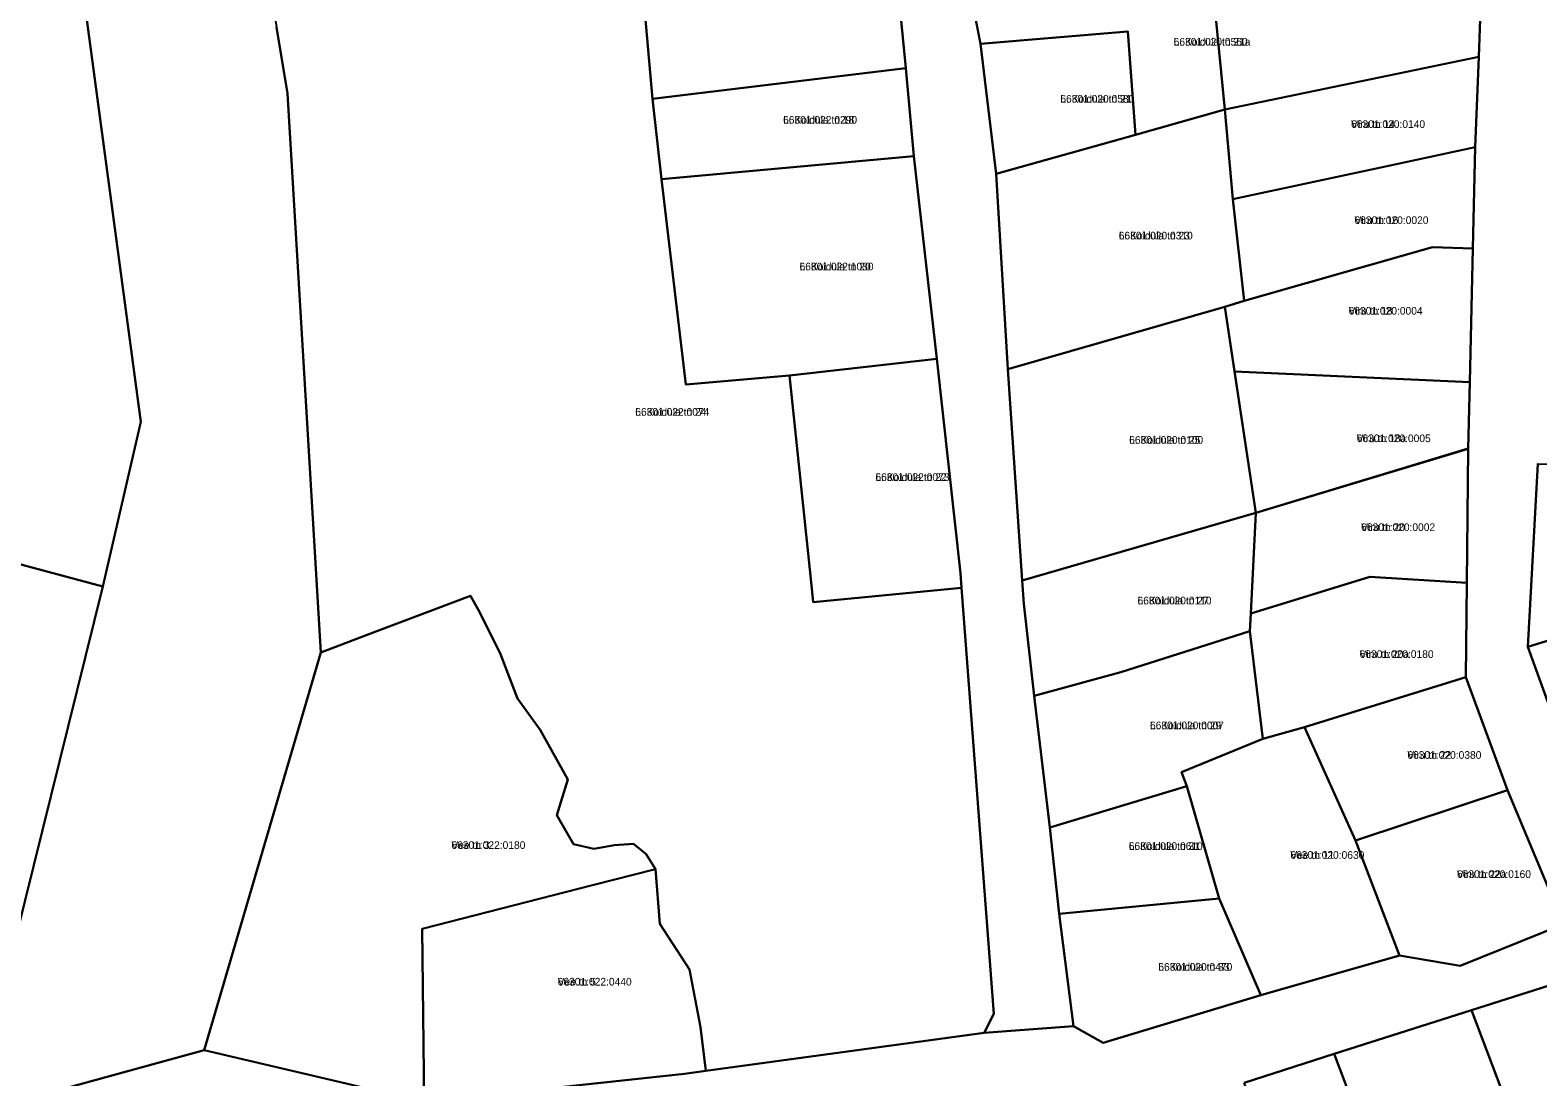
# Model space of a CAD drawing. Extents: x 632278 to 636344, y 6578401 to 6583362.
# Drawn here: x 634226.1 to 634521.7, y 6580277.2 to 6580482.5 of the extents above; entities that cross this region are included whole.
import ezdxf

# ---------------------------------------------------------------- set-up
doc = ezdxf.new("R2010")
doc.units = 0
for name, color, linetype in [('L_AADRESS', 7, 'Continuous'), ('PIIR', 7, 'Continuous'), ('TUNNUS', 7, 'Continuous')]:
    doc.layers.add(name, color=color, linetype=linetype)

msp = doc.modelspace()

# ---------------------------------------------------------------- linework, layer by layer
at = {"layer": 'PIIR'}
for points in [[(634225.23, 6581067.6), (634226.68, 6581036.58), (634227.15, 6581025.28), (634228.16, 6581005.67), (634228.8, 6580993.57), (634229.91, 6580974.72), (634244.55, 6580754.47), (634246.36, 6580732.87), (634249.81, 6580666.52), (634250.81, 6580645.38), (634251.04, 6580641.51), (634252.34, 6580620.25), (634253.83, 6580589.78), (634265.55, 6580590.45), (634266.51, 6580570.25), (634267.07, 6580555.4), (634269.03, 6580516.69), (634274.45, 6580483.07), (634276.55, 6580470.05), (634283.11, 6580360.46), (634260.23, 6580282.49), (634233.12, 6580275.05), (634231.27, 6580268.29), (634222.04, 6580222.66)], [(634526.67, 6580307.21), (634515.73, 6580333.47), (634507.57, 6580355.65), (634507.77, 6580374.1), (634507.99, 6580400.42), (634508, 6580400.43), (634508.3, 6580413.48), (634508.93, 6580439.68), (634509.35, 6580459.54), (634510.12, 6580477.29), (634511.32, 6580512.4), (634511.77, 6580518.86), (634513.89, 6580546.25), (634515.85, 6580575.04), (634516.75, 6580605.53), (634519.64, 6580660.19), (634521.37, 6580706.15), (634531.46, 6580696.5)], [(634220.01, 6580291.27), (634240.38, 6580373.39), (634247.86, 6580405.68), (634225.27, 6580573.66)], [(634411.11, 6580486.45), (634412.41, 6580479.83), (634415.51, 6580454.35), (634417.77, 6580416), (634420.6, 6580374.56), (634420.92, 6580370.01), (634422.93, 6580351.93), (634426.03, 6580326.16), (634427.86, 6580309.24), (634430.64, 6580287.21), (634413.16, 6580285.87), (634415.04, 6580289.63), (634408.7, 6580373.13), (634408.48, 6580376), (634403.88, 6580418.04), (634399.34, 6580457.77), (634397.78, 6580475.03), (634395.68, 6580496.5)], [(634346.16, 6580491.24), (634348.14, 6580469.06), (634349.9, 6580453.29), (634354.65, 6580413.01), (634374.96, 6580414.78), (634379.36, 6580372.99), (634379.61, 6580370.34), (634408.7, 6580373.13), (634415.04, 6580289.63), (634413.16, 6580285.87), (634364.33, 6580279.21), (634358.57, 6580278.43), (634357.56, 6580287.01), (634355.4, 6580298.27), (634349.53, 6580307.22), (634348.72, 6580317.96), (634346.85, 6580320.89), (634344.43, 6580322.96), (634340.66, 6580322.67), (634336.65, 6580321.94), (634332.63, 6580322.9), (634329.35, 6580328.55), (634331.55, 6580335.58), (634326.09, 6580345.26), (634321.64, 6580351.43), (634318.31, 6580360.16), (634314.27, 6580368.32), (634312.47, 6580371.55), (634293.57, 6580364.44), (634283.11, 6580360.46), (634276.55, 6580470.05), (634274.45, 6580483.07)], [(634521.68, 6580397.48), (634519.71, 6580361.56), (634529.07, 6580335.73)], [(634233.12, 6580275.05), (634260.23, 6580282.49), (634303.37, 6580272.33), (634354.37, 6580277.83), (634358.57, 6580278.43), (634364.33, 6580279.21), (634413.16, 6580285.87), (634430.64, 6580287.21), (634436.43, 6580283.88), (634467.33, 6580293.27), (634494.51, 6580301.07), (634506.43, 6580299.02), (634526.67, 6580307.21)], [(634530.69, 6580297.31), (634508.64, 6580290.29), (634481.72, 6580281.73), (634464.09, 6580276.05)]]:
    msp.add_lwpolyline(points, dxfattribs=at)
for points in [[(634105.62, 6580560.24), (634104.57, 6580571.84), (634217.05, 6580579.98), (634220.12, 6580579.79), (634223.06, 6580577.61), (634225.27, 6580573.66), (634247.86, 6580405.68), (634240.38, 6580373.39), (634180.67, 6580389.44), (634076.26, 6580417.52), (634075.51, 6580432.84), (634074.29, 6580470.06), (634073, 6580499.74), (634094.48, 6580500.93), (634090.58, 6580520.33), (634095.58, 6580539.25)], [(634457.38, 6580496.94), (634457.52, 6580500.28), (634511.32, 6580512.4), (634510.12, 6580477.29), (634460.29, 6580466.92)], [(634346.16, 6580491.24), (634355.82, 6580492.47), (634395.68, 6580496.5), (634397.78, 6580475.03), (634348.14, 6580469.06)], [(634441.27, 6580482.24), (634412.41, 6580479.83), (634411.11, 6580486.45), (634457.38, 6580496.94), (634460.29, 6580466.92), (634442.77, 6580462)], [(634412.41, 6580479.83), (634441.27, 6580482.24), (634442.77, 6580462), (634415.51, 6580454.35)], [(634460.29, 6580466.92), (634510.12, 6580477.29), (634509.35, 6580459.54), (634493.61, 6580456.13), (634461.86, 6580449.36)], [(634399.34, 6580457.77), (634349.9, 6580453.29), (634348.14, 6580469.06), (634397.78, 6580475.03)], [(634415.51, 6580454.35), (634442.77, 6580462), (634460.29, 6580466.92), (634461.86, 6580449.36), (634464.1, 6580429.42), (634460.3, 6580428.22), (634417.77, 6580416)], [(634461.86, 6580449.36), (634493.61, 6580456.13), (634509.35, 6580459.54), (634508.93, 6580439.67), (634501.01, 6580439.94), (634464.1, 6580429.42)], [(634349.9, 6580453.29), (634399.34, 6580457.77), (634403.88, 6580418.04), (634374.96, 6580414.78), (634354.65, 6580413.01)], [(634508.93, 6580439.67), (634508.3, 6580413.48), (634462.21, 6580415.57), (634460.3, 6580428.22), (634464.1, 6580429.41), (634501.01, 6580439.94)], [(634417.77, 6580416), (634460.3, 6580428.22), (634466.39, 6580387.85), (634420.6, 6580374.56)], [(634374.96, 6580414.78), (634403.88, 6580418.04), (634408.48, 6580376), (634408.7, 6580373.13), (634379.61, 6580370.34), (634379.36, 6580372.99)], [(634508.3, 6580413.48), (634508, 6580400.43), (634466.39, 6580387.85), (634462.21, 6580415.57)], [(634466.39, 6580387.85), (634507.99, 6580400.42), (634507.77, 6580374.1), (634488.7, 6580375.27), (634465.37, 6580368.13)], [(634519.71, 6580361.56), (634521.68, 6580397.48), (634530.9, 6580397.19), (634530.67, 6580392.63), (634532.84, 6580392.55), (634539.75, 6580392.96), (634544.27, 6580392.91), (634544.18, 6580391.17), (634594.77, 6580397.74), (634597.67, 6580387.25), (634596.4, 6580386.84), (634570.31, 6580378.49), (634541.88, 6580368.41)], [(634180.67, 6580389.44), (634240.38, 6580373.39), (634220.01, 6580291.27), (634216.86, 6580290.73), (634214.42, 6580290.78), (634210.6, 6580291.52), (634187.14, 6580297.94), (634135.36, 6580312.18), (634150.72, 6580367.76), (634173.04, 6580361.59)], [(634422.93, 6580351.93), (634420.92, 6580370.01), (634420.6, 6580374.56), (634466.39, 6580387.85), (634465.37, 6580368.13), (634465.19, 6580364.66), (634439.93, 6580356.57)], [(634507.57, 6580355.65), (634475.92, 6580345.84), (634467.77, 6580343.51), (634465.19, 6580364.66), (634465.37, 6580368.13), (634488.7, 6580375.27), (634507.77, 6580374.1)], [(634283.11, 6580360.46), (634293.57, 6580364.44), (634312.47, 6580371.55), (634314.27, 6580368.32), (634318.31, 6580360.16), (634321.64, 6580351.43), (634326.09, 6580345.26), (634331.55, 6580335.58), (634329.35, 6580328.55), (634332.63, 6580322.9), (634336.65, 6580321.94), (634340.66, 6580322.67), (634344.43, 6580322.96), (634346.85, 6580320.89), (634348.72, 6580317.96), (634336.36, 6580314.86), (634302.95, 6580306.26), (634303.37, 6580272.33), (634260.23, 6580282.49)], [(634519.71, 6580361.56), (634541.88, 6580368.41), (634552.77, 6580343.21), (634529.07, 6580335.73)], [(634422.93, 6580351.93), (634439.93, 6580356.57), (634465.19, 6580364.66), (634467.77, 6580343.51), (634451.8, 6580337), (634452.89, 6580334.25), (634426.03, 6580326.16)], [(634475.92, 6580345.84), (634507.57, 6580355.65), (634515.73, 6580333.47), (634485.9, 6580323.58)], [(634459.17, 6580312.24), (634452.89, 6580334.25), (634451.8, 6580337), (634467.77, 6580343.51), (634475.92, 6580345.84), (634485.9, 6580323.58), (634494.51, 6580301.07), (634467.33, 6580293.27)], [(634426.03, 6580326.16), (634452.89, 6580334.25), (634459.17, 6580312.24), (634427.86, 6580309.24)], [(634506.43, 6580299.02), (634494.51, 6580301.07), (634485.9, 6580323.58), (634515.73, 6580333.47), (634526.67, 6580307.21)], [(634302.95, 6580306.26), (634336.36, 6580314.86), (634348.72, 6580317.96), (634349.53, 6580307.22), (634355.4, 6580298.27), (634357.56, 6580287.01), (634358.57, 6580278.43), (634354.37, 6580277.83), (634303.37, 6580272.33)], [(634430.64, 6580287.21), (634427.86, 6580309.24), (634459.17, 6580312.24), (634467.33, 6580293.27), (634436.43, 6580283.88)], [(634503.41, 6580252.42), (634513.48, 6580256.03), (634508.53, 6580268.79), (634515.67, 6580271.8), (634508.64, 6580290.29), (634530.69, 6580297.31), (634545.01, 6580262.39), (634506.08, 6580246.02)], [(634508.64, 6580290.29), (634515.67, 6580271.8), (634508.53, 6580268.79), (634513.48, 6580256.03), (634503.41, 6580252.42), (634494, 6580249.01), (634483.94, 6580275.88), (634481.72, 6580281.73)], [(634464.09, 6580276.05), (634481.72, 6580281.73), (634483.94, 6580275.88), (634494, 6580249.01), (634477.06, 6580242.99)]]:
    msp.add_lwpolyline(points, close=True, dxfattribs=at)

# ---------------------------------------------------------------- texts
at = {"layer": 'L_AADRESS'}
for s, p in [('L. Koidula tn 21a', (634450.27, 6580479.47)), ('L. Koidula tn 21', (634428.06, 6580468.29)), ('L. Koidula tn 18', (634373.72, 6580464.16)), ('Viru tn 14', (634485.06, 6580463.32)), ('Viru tn 16', (634485.72, 6580444.48)), ('L. Koidula tn 23', (634439.51, 6580441.46)), ('L. Koidula tn 20', (634376.95, 6580435.39)), ('Viru tn 18', (634484.57, 6580426.71)), ('L. Koidula tn 24', (634344.75, 6580406.89)), ('L. Koidula tn 25', (634441.56, 6580401.39)), ('Viru tn 18a', (634486.16, 6580401.71)), ('L. Koidula tn 22', (634391.83, 6580394.1)), ('Viru tn 20', (634487.03, 6580384.28)), ('L. Koidula tn 27', (634443.2, 6580369.89)), ('Viru tn 20a', (634486.72, 6580359.39)), ('L. Koidula tn 29', (634445.63, 6580345.41)), ('Viru tn 22', (634496.09, 6580339.61)), ('Vee tn 3', (634308.71, 6580321.94)), ('L. Koidula tn 31', (634441.48, 6580321.74)), ('Vee tn 11', (634473.15, 6580320)), ('Viru tn 22a', (634505.81, 6580316.24)), ('L. Koidula tn 33', (634447.27, 6580298.06)), ('Vee tn 5', (634329.54, 6580295.15))]:
    msp.add_text(s, height=1.5, dxfattribs=at).set_placement(p)
at = {"layer": 'TUNNUS'}
for s, p in [('66301:020:0560', (634450.27, 6580479.47)), ('66301:020:0580', (634428.06, 6580468.29)), ('66301:022:0290', (634373.72, 6580464.16)), ('66301:020:0140', (634485.06, 6580463.32)), ('66301:020:0020', (634485.72, 6580444.48)), ('66301:020:0310', (634439.51, 6580441.46)), ('66301:022:1030', (634376.95, 6580435.39)), ('66301:020:0004', (634484.57, 6580426.71)), ('66301:022:0074', (634344.75, 6580406.89)), ('66301:020:0100', (634441.56, 6580401.39)), ('66301:020:0005', (634486.16, 6580401.71)), ('66301:022:0073', (634391.83, 6580394.1)), ('66301:020:0002', (634487.03, 6580384.28)), ('66301:020:0110', (634443.2, 6580369.89)), ('66301:020:0180', (634486.72, 6580359.39)), ('66301:020:0007', (634445.63, 6580345.41)), ('66301:020:0380', (634496.09, 6580339.61)), ('66301:022:0180', (634308.71, 6580321.94)), ('66301:020:0610', (634441.48, 6580321.74)), ('66301:020:0630', (634473.15, 6580320)), ('66301:020:0160', (634505.81, 6580316.24)), ('66301:020:0470', (634447.27, 6580298.06)), ('66301:022:0440', (634329.54, 6580295.15))]:
    msp.add_text(s, height=1.5, dxfattribs=at).set_placement(p)

doc.saveas('drawing.dxf')
